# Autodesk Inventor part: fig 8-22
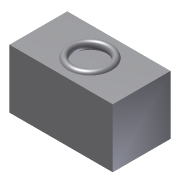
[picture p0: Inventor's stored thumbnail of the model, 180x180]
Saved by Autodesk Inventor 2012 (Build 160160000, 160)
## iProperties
Created: 2011-07
Part Number: fig 8-22
Material: Default
Document SubType Name: Modeling
Designer: CadCim
Density: 1 g/cm^3
Author: CadCim
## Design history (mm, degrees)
sketch "Sketch1"
  geometry: L1 (-18, 10)-(7, 10); L2 (7, 10)-(7, -4); L3 (7, -4)-(-18, -4); L4 (-18, -4)-(-18, 10); 1 further point
  constraints: 8 end point, 2 parallel, 1 horizontal, 1 perpendicular
extrude "Extrusion1" new body sketch "Sketch1" distance "d0" = 14.25; taper "d1" = 0 deg
sketch "Sketch2"
  geometry: C1 r 4.5 at (-5.5, 3); 1 further point
  constraints: 1 centre point
extrude "Extrusion2" cut sketch "Sketch2" distance "d2" = 1.5; taper "d3" = 0 deg
workplane "Work Plane2"
sketch "Sketch4"
  geometry: C1 r 1 at (9, -14); 1 further point
  constraints: 1 centre point
sketch "3D Sketch1"
sweep "Sweep1" sketch "Sketch4", "3D Sketch1" dims "d5" = 0
body "Solid1"
other parameters: "d4" = -4.25
